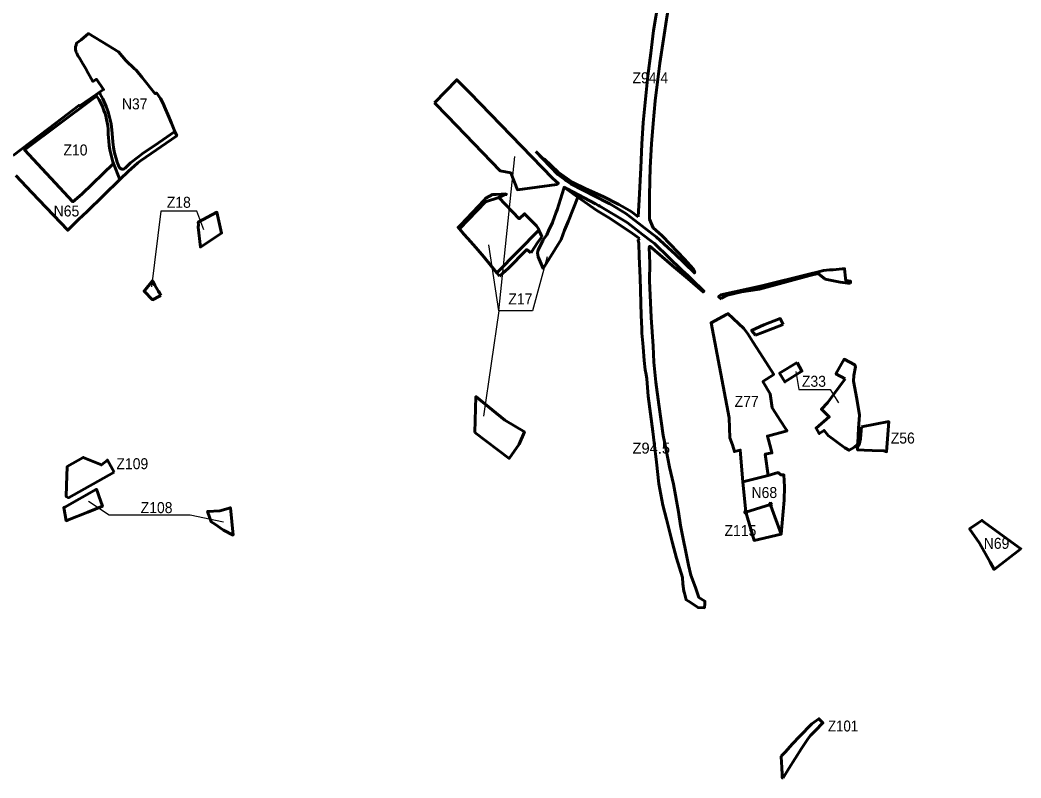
# Model space of a CAD drawing. Extents: x -650277 to -643420, y -1073980 to -1066720.
# Drawn here: x -646722 to -644537, y -1073665 to -1072009 of the extents above; entities that cross this region are included whole.
import ezdxf

# ---------------------------------------------------------------- set-up
doc = ezdxf.new("R2010")
doc.units = 0
doc.header["$LTSCALE"] = 9.6
doc.header["$PDMODE"] = 32
doc.header["$PDSIZE"] = 4.8
for name, color, linetype, lineweight in [('1', 7, 'Continuous', 60), ('15', 7, 'Continuous', 60), ('3', 7, 'Continuous', 60), ('34', 7, 'Continuous', 60), ('35', 7, 'Continuous', 60), ('40', 7, 'Continuous', 60), ('42', 7, 'Continuous', 60), ('45', 7, 'Continuous', 60), ('60', 7, 'Continuous', 60), ('63', 7, 'Continuous', 25), ('9', 7, 'Continuous', 60)]:
    doc.layers.add(name, color=color, linetype=linetype, lineweight=lineweight)

msp = doc.modelspace()

# ---------------------------------------------------------------- linework, layer by layer
at = {"layer": '1'}
msp.add_line((-646417.787, -1072612.168), (-646414.77, -1072610.61), dxfattribs=at)
for points in [[(-645817.219, -1072189.975), (-645768.649, -1072139.283), (-645740.45, -1072168.23), (-645559.34, -1072354.42), (-645546.82, -1072365.72), (-645550.41, -1072368.47), (-645636.37, -1072379.57), (-645650.78, -1072342.73), (-645674, -1072338), (-645789.298, -1072218.833)], [(-646606.848, -1072405.785), (-646587.666, -1072389.082), (-646518.208, -1072321.92), (-646519.417, -1072318.408), (-646522.007, -1072309.932), (-646524.282, -1072300.849), (-646526, -1072292.201), (-646527.5, -1072282.657), (-646528.566, -1072273.308), (-646529.182, -1072265.941), (-646529.607, -1072258.124), (-646530.188, -1072247.442), (-646530.892, -1072239.747), (-646531.93, -1072232.861), (-646533.286, -1072226.031), (-646535.344, -1072217.844), (-646536.772, -1072213.218), (-646539.168, -1072206.122), (-646539.168, -1072206.122), (-646542.484, -1072197.985), (-646546.09, -1072190.428), (-646549.793, -1072183.38), (-646554.56, -1072175.629), (-646555.051, -1072174.933), (-646563.299, -1072181.091), (-646710.684, -1072291.133), (-646712.634, -1072292.59)], [(-645503.98, -1072395.64), (-645532.75, -1072375.41), (-645535.05, -1072376.72), (-645549.6, -1072423.39), (-645551.54, -1072428.66), (-645559.92, -1072451.41), (-645568.38, -1072469.68), (-645572.13, -1072477.78), (-645579.92, -1072489.22), (-645581.13, -1072491), (-645591.06, -1072511.06), (-645592.08, -1072517.43), (-645591.03, -1072526.14), (-645579.76, -1072551.45), (-645541.09, -1072487.98), (-645533.15, -1072468.21), (-645524.87, -1072447.61)], [(-645588.78, -1072467), (-645594.83, -1072458.48), (-645620.56, -1072432), (-645632.1, -1072442.93), (-645676.53, -1072396.16), (-645706.039, -1072405.769), (-645763.06, -1072465.26), (-645753.128, -1072476.383), (-645744.38, -1072486.18), (-645726.95, -1072505.7), (-645709.92, -1072526.3), (-645694.51, -1072544.93), (-645680.87, -1072561.42)], [(-646333.34, -1072461.67), (-646328.45, -1072504.81), (-646282.47, -1072474.34), (-646292.44, -1072428.89), (-646333.33, -1072450.12), (-646332.68, -1072456.19)], [(-645729.36, -1072909.65), (-645654.16, -1072966.3), (-645632.23, -1072935.28), (-645620.92, -1072908.65), (-645663.52, -1072882.58), (-645726.9, -1072831.5)]]:
    msp.add_lwpolyline(points, close=True, dxfattribs=at)
for points in [[(-646420.36, -1072601.78), (-646427.95, -1072588.07), (-646432.57, -1072579.75), (-646433.36, -1072578.45), (-646451.458, -1072601.008), (-646433.024, -1072620.04), (-646417.787, -1072612.168)], [(-646414.77, -1072610.61), (-646419.11, -1072602.03), (-646419.47, -1072601.31), (-646419.02, -1072604.18), (-646420.36, -1072601.78)]]:
    msp.add_lwpolyline(points, dxfattribs=at)
at = {"layer": '15'}
msp.add_lwpolyline([(-646529.182, -1072265.941), (-646528.566, -1072273.308), (-646527.5, -1072282.657), (-646526, -1072292.201), (-646524.282, -1072300.849), (-646522.007, -1072309.932), (-646519.417, -1072318.408), (-646518.208, -1072321.92), (-646504.244, -1072357.026), (-646485.656, -1072338.908), (-646473.069, -1072327.765), (-646465.227, -1072321.127), (-646459.03, -1072316.137), (-646380.12, -1072261.44), (-646384.056, -1072252.138), (-646420.085, -1072276.737), (-646455.557, -1072301.131), (-646462.79, -1072306.784), (-646480.923, -1072320.667), (-646486.273, -1072325.526), (-646492.813, -1072332.07), (-646494.794, -1072333.558), (-646497.569, -1072334.55), (-646500.244, -1072334.45), (-646503.018, -1072333.459), (-646504.802, -1072331.971), (-646506.189, -1072329.889), (-646509.954, -1072319.377), (-646512.729, -1072311.048), (-646515.305, -1072301.925), (-646516.692, -1072294.983), (-646518.079, -1072287.051), (-646519.756, -1072274.861), (-646521.051, -1072256.707), (-646521.646, -1072248.378), (-646523.628, -1072235.883), (-646526.798, -1072221.011), (-646530.167, -1072209.31), (-646534.527, -1072197.411), (-646541.822, -1072181.102), (-646547.606, -1072170.835), (-646548.676, -1072166.737), (-646556.693, -1072172.16), (-646555.051, -1072174.933), (-646554.56, -1072175.629), (-646549.793, -1072183.38), (-646546.09, -1072190.428), (-646542.484, -1072197.985), (-646539.168, -1072206.122), (-646536.772, -1072213.218), (-646535.344, -1072217.844), (-646533.286, -1072226.031), (-646531.93, -1072232.861), (-646530.892, -1072239.747), (-646530.188, -1072247.442), (-646529.607, -1072258.124)], close=True, dxfattribs=at)
for points in [[(-645661.3, -1072388.74), (-645682.59, -1072389.76), (-645690.37, -1072390.13), (-645705, -1072398.19), (-645708.94, -1072402.11)], [(-645676.53, -1072396.16), (-645676.53, -1072396.16), (-645665.32, -1072390.32), (-645660.16, -1072389.95), (-645661.3, -1072388.74)], [(-645708.94, -1072402.11), (-645760.02, -1072455.94), (-645765.95, -1072462.03), (-645763.06, -1072465.26)], [(-645763.06, -1072465.26), (-645706.039, -1072405.769), (-645676.53, -1072396.16)], [(-645582.84, -1072481.71), (-645584.46, -1072478.58), (-645589.862, -1072468.109), (-645680.87, -1072561.42), (-645675.13, -1072568.36)], [(-645607.07, -1072517.61), (-645605.95, -1072515.95), (-645604.82, -1072514.3), (-645592.9, -1072496.52), (-645583.13, -1072482.13), (-645582.84, -1072481.71)], [(-645675.13, -1072568.36), (-645655.65, -1072550.62), (-645617.87, -1072512.12), (-645615.95, -1072510.16), (-645607.07, -1072517.61)], [(-644926.81, -1072552.51), (-644946.57, -1072554.22), (-644954.57, -1072554.43), (-644967.97, -1072556.17), (-644978.56, -1072558.74), (-644999.72, -1072564.24), (-645102.73, -1072589.74), (-645192.06, -1072609.19), (-645197.044, -1072612.821), (-645190.71, -1072618.6)], [(-645147.13, -1072602.79), (-645107.58, -1072596.47), (-644997.92, -1072567.23), (-644979.55, -1072562.44), (-644963.97, -1072574.57)], [(-644919.75, -1072572.43), (-644921.84, -1072552.03), (-644926.81, -1072552.51)], [(-644963.97, -1072574.57), (-644931.48, -1072581.26), (-644909.02, -1072584.28)], [(-644909.02, -1072584.28), (-644908.59, -1072579.51), (-644919.23, -1072577.46), (-644919.75, -1072572.43)], [(-645190.71, -1072618.6), (-645190.59, -1072616.28), (-645179.6, -1072610.94), (-645177.56, -1072609.89), (-645147.13, -1072602.79)], [(-645056.08, -1072674.07), (-645062.131, -1072660.856), (-645098.016, -1072674.425), (-645115.56, -1072682.406), (-645124.933, -1072686.721), (-645116.11, -1072697.15)], [(-645116.11, -1072697.15), (-645100.9, -1072691.31), (-645056.08, -1072674.07)]]:
    msp.add_lwpolyline(points, dxfattribs=at)
at = {"layer": '3'}
for points in [[(-645025.61, -1072757.17), (-645063.6, -1072780.26), (-645051.94, -1072799.21), (-645015.02, -1072776.01)], [(-645054.12, -1073057.62), (-645052.94, -1073028.58), (-645054.44, -1073002.54), (-645060.95, -1073002.68), (-645066.66, -1072997.3), (-645074.333, -1072999.365), (-645088.62, -1073003.45), (-645144.37, -1073017.64), (-645137.5, -1073083.97), (-645083.681, -1073066.962), (-645082.6, -1073069.93), (-645060.1, -1073131.68)]]:
    msp.add_lwpolyline(points, close=True, dxfattribs=at)
for points in [[(-644902.18, -1072797.88), (-644901.35, -1072785.36), (-644898.29, -1072766.55), (-644899.2, -1072762.14), (-644922.88, -1072749.97), (-644940.8, -1072781.48), (-644920.46, -1072792.92)], [(-644920.46, -1072792.92), (-644945.2, -1072826.3), (-644959.24, -1072844.92), (-644972.28, -1072859.02), (-644955.49, -1072875.78), (-644983.93, -1072900.24), (-644977.16, -1072912.11), (-644966.57, -1072905.23), (-644957.79, -1072916.73), (-644921.18, -1072943.17), (-644911.87, -1072948.76), (-644900.2, -1072941.67), (-644893.77, -1072935.88), (-644892.86, -1072932.6), (-644891.2, -1072900.09), (-644889.11, -1072871.66), (-644895.32, -1072836.6), (-644902.18, -1072797.88)], [(-645137.5, -1073083.97), (-645119.34, -1073145.61), (-645060.1, -1073131.68), (-645082.6, -1073069.93), (-645083.681, -1073066.962)]]:
    msp.add_lwpolyline(points, dxfattribs=at)
for p in [(-645083.681, -1073066.962), (-645137.5, -1073083.97)]:
    msp.add_point(p, dxfattribs=at)
at = {"layer": '34'}
for points in [[(-646574.156, -1073083.691), (-646542.62, -1073071.1), (-646550.01, -1073048.55), (-646552.79, -1073041.53), (-646555.79, -1073033.92), (-646624.69, -1073072.66), (-646626.967, -1073073.918), (-646621.38, -1073102.66), (-646620.19, -1073102.14), (-646618.56, -1073101.42)], [(-646298.029, -1073109.723), (-646278.38, -1073123.25), (-646257.09, -1073134.01), (-646262.94, -1073074.15), (-646285.77, -1073081.01), (-646312.87, -1073082.4), (-646305.18, -1073104.8)]]:
    msp.add_lwpolyline(points, close=True, dxfattribs=at)
at = {"layer": '35'}
msp.add_lwpolyline([(-646516.7, -1072996.65), (-646531.46, -1072970.12), (-646544.68, -1072980.62), (-646584.23, -1072964.22), (-646619.48, -1072984.34), (-646620.71, -1073025.49), (-646621.44, -1073049.79), (-646616.55, -1073052.21)], close=True, dxfattribs=at)
at = {"layer": '40'}
msp.add_lwpolyline([(-646507.28, -1072078.4), (-646530.073, -1072064.559), (-646573.05, -1072038.46), (-646588.75, -1072052.06), (-646598.827, -1072059.244), (-646599.86, -1072063.71), (-646601, -1072067.55), (-646601.42, -1072071.01), (-646601.16, -1072074.07), (-646600.8, -1072075.94), (-646600.22, -1072077.86), (-646598.67, -1072081.55), (-646595.86, -1072086.82), (-646593.13, -1072091.01), (-646591.02, -1072094.4), (-646585.08, -1072104.81), (-646583.9, -1072106.42), (-646577.41, -1072117.76), (-646577.08, -1072118.7), (-646563.11, -1072143.03), (-646555.49, -1072138.17), (-646539.94, -1072160.83), (-646548.676, -1072166.737), (-646547.606, -1072170.835), (-646541.822, -1072181.102), (-646534.527, -1072197.411), (-646530.167, -1072209.31), (-646526.798, -1072221.011), (-646523.628, -1072235.883), (-646521.646, -1072248.378), (-646521.051, -1072256.707), (-646519.756, -1072274.861), (-646518.079, -1072287.051), (-646516.692, -1072294.983), (-646515.305, -1072301.925), (-646512.729, -1072311.048), (-646509.954, -1072319.377), (-646506.189, -1072329.889), (-646504.802, -1072331.971), (-646503.018, -1072333.459), (-646500.244, -1072334.45), (-646497.569, -1072334.55), (-646494.794, -1072333.558), (-646492.813, -1072332.07), (-646486.273, -1072325.526), (-646480.923, -1072320.667), (-646462.79, -1072306.784), (-646455.557, -1072301.131), (-646420.085, -1072276.737), (-646384.056, -1072252.138), (-646391.77, -1072233.91), (-646399.6, -1072215.39), (-646404.67, -1072203.42), (-646410.68, -1072189.36), (-646415.84, -1072180.43), (-646424.56, -1072167.96), (-646426.98, -1072169.74), (-646455.75, -1072134.29), (-646468.35, -1072118.76), (-646469.41, -1072117.44), (-646472.72, -1072115.38), (-646491.69, -1072097.45)], close=True, dxfattribs=at)
at = {"layer": '42'}
for points in [[(-645817.219, -1072189.975), (-645768.649, -1072139.283), (-645740.45, -1072168.23), (-645559.34, -1072354.42), (-645546.82, -1072365.72), (-645550.41, -1072368.47), (-645636.37, -1072379.57), (-645650.78, -1072342.73), (-645674, -1072338), (-645789.298, -1072218.833)], [(-644536.62, -1073164.33), (-644536.62, -1073164.33), (-644622.03, -1073101.88), (-644622.03, -1073101.88), (-644630.58, -1073107.78), (-644648.95, -1073120.47), (-644627.53, -1073151.26), (-644604.13, -1073193), (-644595.18, -1073208.98)]]:
    msp.add_lwpolyline(points, close=True, dxfattribs=at)
at = {"layer": '45'}
msp.add_lwpolyline([(-646731.82, -1072348.2), (-646696.83, -1072385.81), (-646618.158, -1072468.098), (-646594.606, -1072444.422), (-646575.792, -1072426.789), (-646504.244, -1072357.026), (-646518.208, -1072321.92), (-646587.666, -1072389.082), (-646606.848, -1072405.785), (-646712.634, -1072292.59), (-646563.299, -1072181.091), (-646555.051, -1072174.933), (-646556.693, -1072172.16), (-646592.2, -1072196.17), (-646593.85, -1072195.48), (-646643.55, -1072233.5), (-646737.449, -1072305.019)], dxfattribs=at)
at = {"layer": '60'}
for points in [[(-645339.904, -1072462.677), (-645347.551, -1072443.527), (-645347.677, -1072391.355), (-645346.62, -1072330.914), (-645343.458, -1072278.998), (-645339.908, -1072235.158), (-645335.367, -1072185.207), (-645325.498, -1072102.789), (-645309.01, -1071998.147), (-645285.617, -1071875.733), (-645244.798, -1071696.585), (-645235.793, -1071663.703), (-645230.436, -1071634.261), (-645227.905, -1071625.277), (-645222.48, -1071606.08)], [(-645313.153, -1071883.081), (-645326.343, -1071952.807), (-645334.118, -1072001.954), (-645339.455, -1072031.565), (-645344.819, -1072081.225), (-645351.358, -1072130.815), (-645361.317, -1072232.824), (-645364.435, -1072280.268), (-645366.951, -1072331.609), (-645370.624, -1072401.447), (-645372.228, -1072438.764)], [(-645372.228, -1072438.764), (-645387.894, -1072427.453), (-645401.441, -1072419.033), (-645414.631, -1072411.611), (-645448.831, -1072394.325), (-645488.64, -1072376.782), (-645515.437, -1072363.447), (-645547.593, -1072340.827), (-645577.33, -1072312.704), (-645579.217, -1072312.425), (-645596.405, -1072296.114)], [(-645596.405, -1072296.114), (-645564.4, -1072328.61), (-645547.72, -1072346.19), (-645532.07, -1072358.01), (-645531.65, -1072358.29), (-645528.27, -1072360.53), (-645519.57, -1072366.3), (-645438.64, -1072408.1)], [(-645533.08, -1072373.71), (-645534.3, -1072374.33), (-645532.75, -1072375.41), (-645503.98, -1072395.64)], [(-645370.226, -1072471.736), (-645396.94, -1072451.44), (-645400.12, -1072449.03), (-645456.52, -1072415.6), (-645459.31, -1072413.95), (-645465.793, -1072410.498), (-645527.33, -1072377.73), (-645533.08, -1072373.71)], [(-645503.98, -1072395.64), (-645462.65, -1072425.01), (-645462.651, -1072425.011), (-645462.646, -1072425.015)], [(-645438.64, -1072408.1), (-645437.6, -1072408.64), (-645434.19, -1072410.67), (-645399.77, -1072431.12), (-645371.356, -1072453.119), (-645342.284, -1072475.625)], [(-645462.646, -1072425.015), (-645433.91, -1072442.56), (-645404.64, -1072461.72), (-645389.731, -1072471.612), (-645369.364, -1072485.931)], [(-645345.079, -1072490.836), (-645362.81, -1072477.37), (-645370.226, -1072471.736)], [(-645342.284, -1072475.625), (-645333.62, -1072482.33), (-645290.76, -1072520.92)], [(-645290.76, -1072520.92), (-645271.74, -1072539.96), (-645249.9, -1072561.25), (-645248.967, -1072559.511), (-645252.768, -1072552.178), (-645265.009, -1072538.358), (-645272.276, -1072530.154), (-645302.303, -1072499.014), (-645320.805, -1072479.495), (-645339.904, -1072462.677)], [(-645369.364, -1072485.931), (-645372.72, -1072490.314), (-645370.928, -1072496.619), (-645370.755, -1072525.734), (-645368.173, -1072571.881), (-645366.022, -1072654.462), (-645364.524, -1072682.575), (-645364.786, -1072692.977), (-645362.708, -1072714.781)], [(-645242, -1072588.6), (-645263.7, -1072567.8), (-645276.93, -1072555.11), (-645306.46, -1072527.08), (-645336.33, -1072497.48), (-645336.887, -1072497.057), (-645345.079, -1072490.836)], [(-645338.023, -1072755.969), (-645339.96, -1072721.587), (-645344.152, -1072658.857), (-645347.795, -1072577.893), (-645347.214, -1072540.97), (-645348.253, -1072505.583), (-645347.292, -1072502.877), (-645298.498, -1072545.352)], [(-645298.498, -1072545.352), (-645263.217, -1072574.314), (-645230.845, -1072602.888), (-645228.96, -1072600.865), (-645241.87, -1072588.722), (-645242, -1072588.6)], [(-645362.708, -1072714.781), (-645361.874, -1072723.527), (-645359.76, -1072752.865), (-645357.272, -1072772.771), (-645355.121, -1072782.993)], [(-645317.65, -1072916.642), (-645322.284, -1072885.085), (-645327.091, -1072848.387), (-645333.718, -1072799.987), (-645338.023, -1072755.969)], [(-645355.121, -1072782.993), (-645354.019, -1072792.454), (-645350.822, -1072830.388), (-645340.345, -1072908.029), (-645337.34, -1072932.073), (-645332.517, -1072974.538), (-645327.554, -1073022.214)], [(-645304.24, -1072985.372), (-645311.772, -1072947.945), (-645317.65, -1072916.642)], [(-645257.842, -1073221.36), (-645262.388, -1073199.409), (-645279.878, -1073113.356), (-645284.269, -1073083.286), (-645295.788, -1073022.556), (-645304.24, -1072985.372)], [(-645327.554, -1073022.214), (-645319.052, -1073068.6), (-645310.558, -1073098.946), (-645297.395, -1073151.294), (-645288.647, -1073184.518), (-645276.125, -1073226.571), (-645275.269, -1073240.71), (-645272.747, -1073256.762), (-645271.518, -1073261.16), (-645267.525, -1073275.443), (-645263.03, -1073278.25), (-645241.72, -1073292.2), (-645227.744, -1073292.736), (-645227.199, -1073283.366), (-645226.847, -1073278.345), (-645239.9, -1073270.025), (-645247.051, -1073248.736), (-645257.842, -1073221.36)]]:
    msp.add_lwpolyline(points, dxfattribs=at)
at = {"layer": '63'}
for q in [(-645642, -1072307), (-645699, -1072500)]:
    msp.add_line((-645677, -1072644), q, dxfattribs=at)
for points in [[(-646321, -1072467), (-646336, -1072426), (-646415, -1072426), (-646435, -1072592)], [(-645571, -1072526), (-645603, -1072644), (-645677, -1072644), (-645710, -1072874)], [(-645027.959, -1072776.842), (-645022, -1072816), (-644953, -1072816), (-644935, -1072845)], [(-646573, -1073060), (-646528, -1073090), (-646351, -1073090), (-646278, -1073105)]]:
    msp.add_lwpolyline(points, dxfattribs=at)
at = {"layer": '9'}
for points in [[(-645144.37, -1073017.64), (-645088.62, -1073003.45), (-645095.04, -1072957.07), (-645080.61, -1072954.43), (-645083.13, -1072944.94), (-645090.34, -1072917.86), (-645047.42, -1072906.05), (-645050.6, -1072901.03), (-645069.55, -1072872.12), (-645071.87, -1072868.45), (-645079.81, -1072855.89), (-645084.47, -1072825.67), (-645100.27, -1072798.46), (-645076.66, -1072783.06), (-645099.58, -1072746.945), (-645121.96, -1072711.68), (-645133.26, -1072694.17), (-645142.1, -1072682.57), (-645176.757, -1072649.968), (-645180.05, -1072651.77), (-645213.34, -1072669.98), (-645174.13, -1072877.93), (-645172.28, -1072921.42), (-645166.48, -1072936.5), (-645162.379, -1072951.55), (-645149.84, -1072948.13)], [(-644884.94, -1072897.19), (-644886.98, -1072923.48), (-644889.65, -1072936.67), (-644893.37, -1072942.61), (-644893.59, -1072947.97), (-644878.86, -1072948.42), (-644861.93, -1072948.94), (-644835.99, -1072949.74), (-644830.25, -1072951.9), (-644825.25, -1072885.96)]]:
    msp.add_lwpolyline(points, close=True, dxfattribs=at)
for points in [[(-645056.06, -1073664.2), (-645043.35, -1073644.04), (-645015.55, -1073599.96), (-645001.267, -1073578.582), (-644996.41, -1073571.97), (-644985.66, -1073560.69), (-644969.117, -1073544.254), (-644977.924, -1073535.072), (-644993.044, -1073546.324), (-645020.11, -1073573.585), (-645035.303, -1073590.199), (-645051.513, -1073608.124), (-645060.009, -1073616.53)], [(-645060.009, -1073616.53), (-645059.35, -1073631.3), (-645058.96, -1073640.09), (-645058.65, -1073647), (-645058.42, -1073652.18), (-645058.01, -1073661.37), (-645057.87, -1073664.55), (-645056.06, -1073664.2)]]:
    msp.add_lwpolyline(points, dxfattribs=at)

# ---------------------------------------------------------------- texts
at = {"layer": '63'}
for s, width, p in [('Z94.4', 0.95, (-645385, -1072147)), ('N37', 0.95, (-646500, -1072204)), ('Z10', 0.95, (-646627.672, -1072304.645)), ('N65', 0.95, (-646649, -1072438)), ('Z18', 0.95, (-646402, -1072419)), ('Z17', 0.95, (-645656, -1072630)), ('Z33', 0.95, (-645015, -1072810)), ('Z77', 0.95, (-645162, -1072854)), ('Z56', 0.95, (-644821, -1072934)), ('Z109', 0.95, (-646512, -1072990)), ('N68', 0.95, (-645125, -1073053)), ('Z108', 0.95, (-646459, -1073086)), ('Z115', 0.95, (-645184, -1073136)), ('N69', 0.95, (-644618, -1073164)), ('Z101', 0.9, (-644958, -1073563))]:
    msp.add_text(s, height=24, dxfattribs=dict(at, width=width)).set_placement(p)
msp.add_text('Z94.5', height=24, dxfattribs=at).set_placement((-645385, -1072956))

doc.saveas('drawing.dxf')
